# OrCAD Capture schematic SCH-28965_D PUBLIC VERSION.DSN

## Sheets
1 TITLE, TOC & REV: title: SEN-GEN6-SKT; rev: D; company: NXP Semiconductors; note: SCH-28965 PDF: SPF-28965; note: 6501 William Cannon Drive West; note: Austin, TX 78735-8598
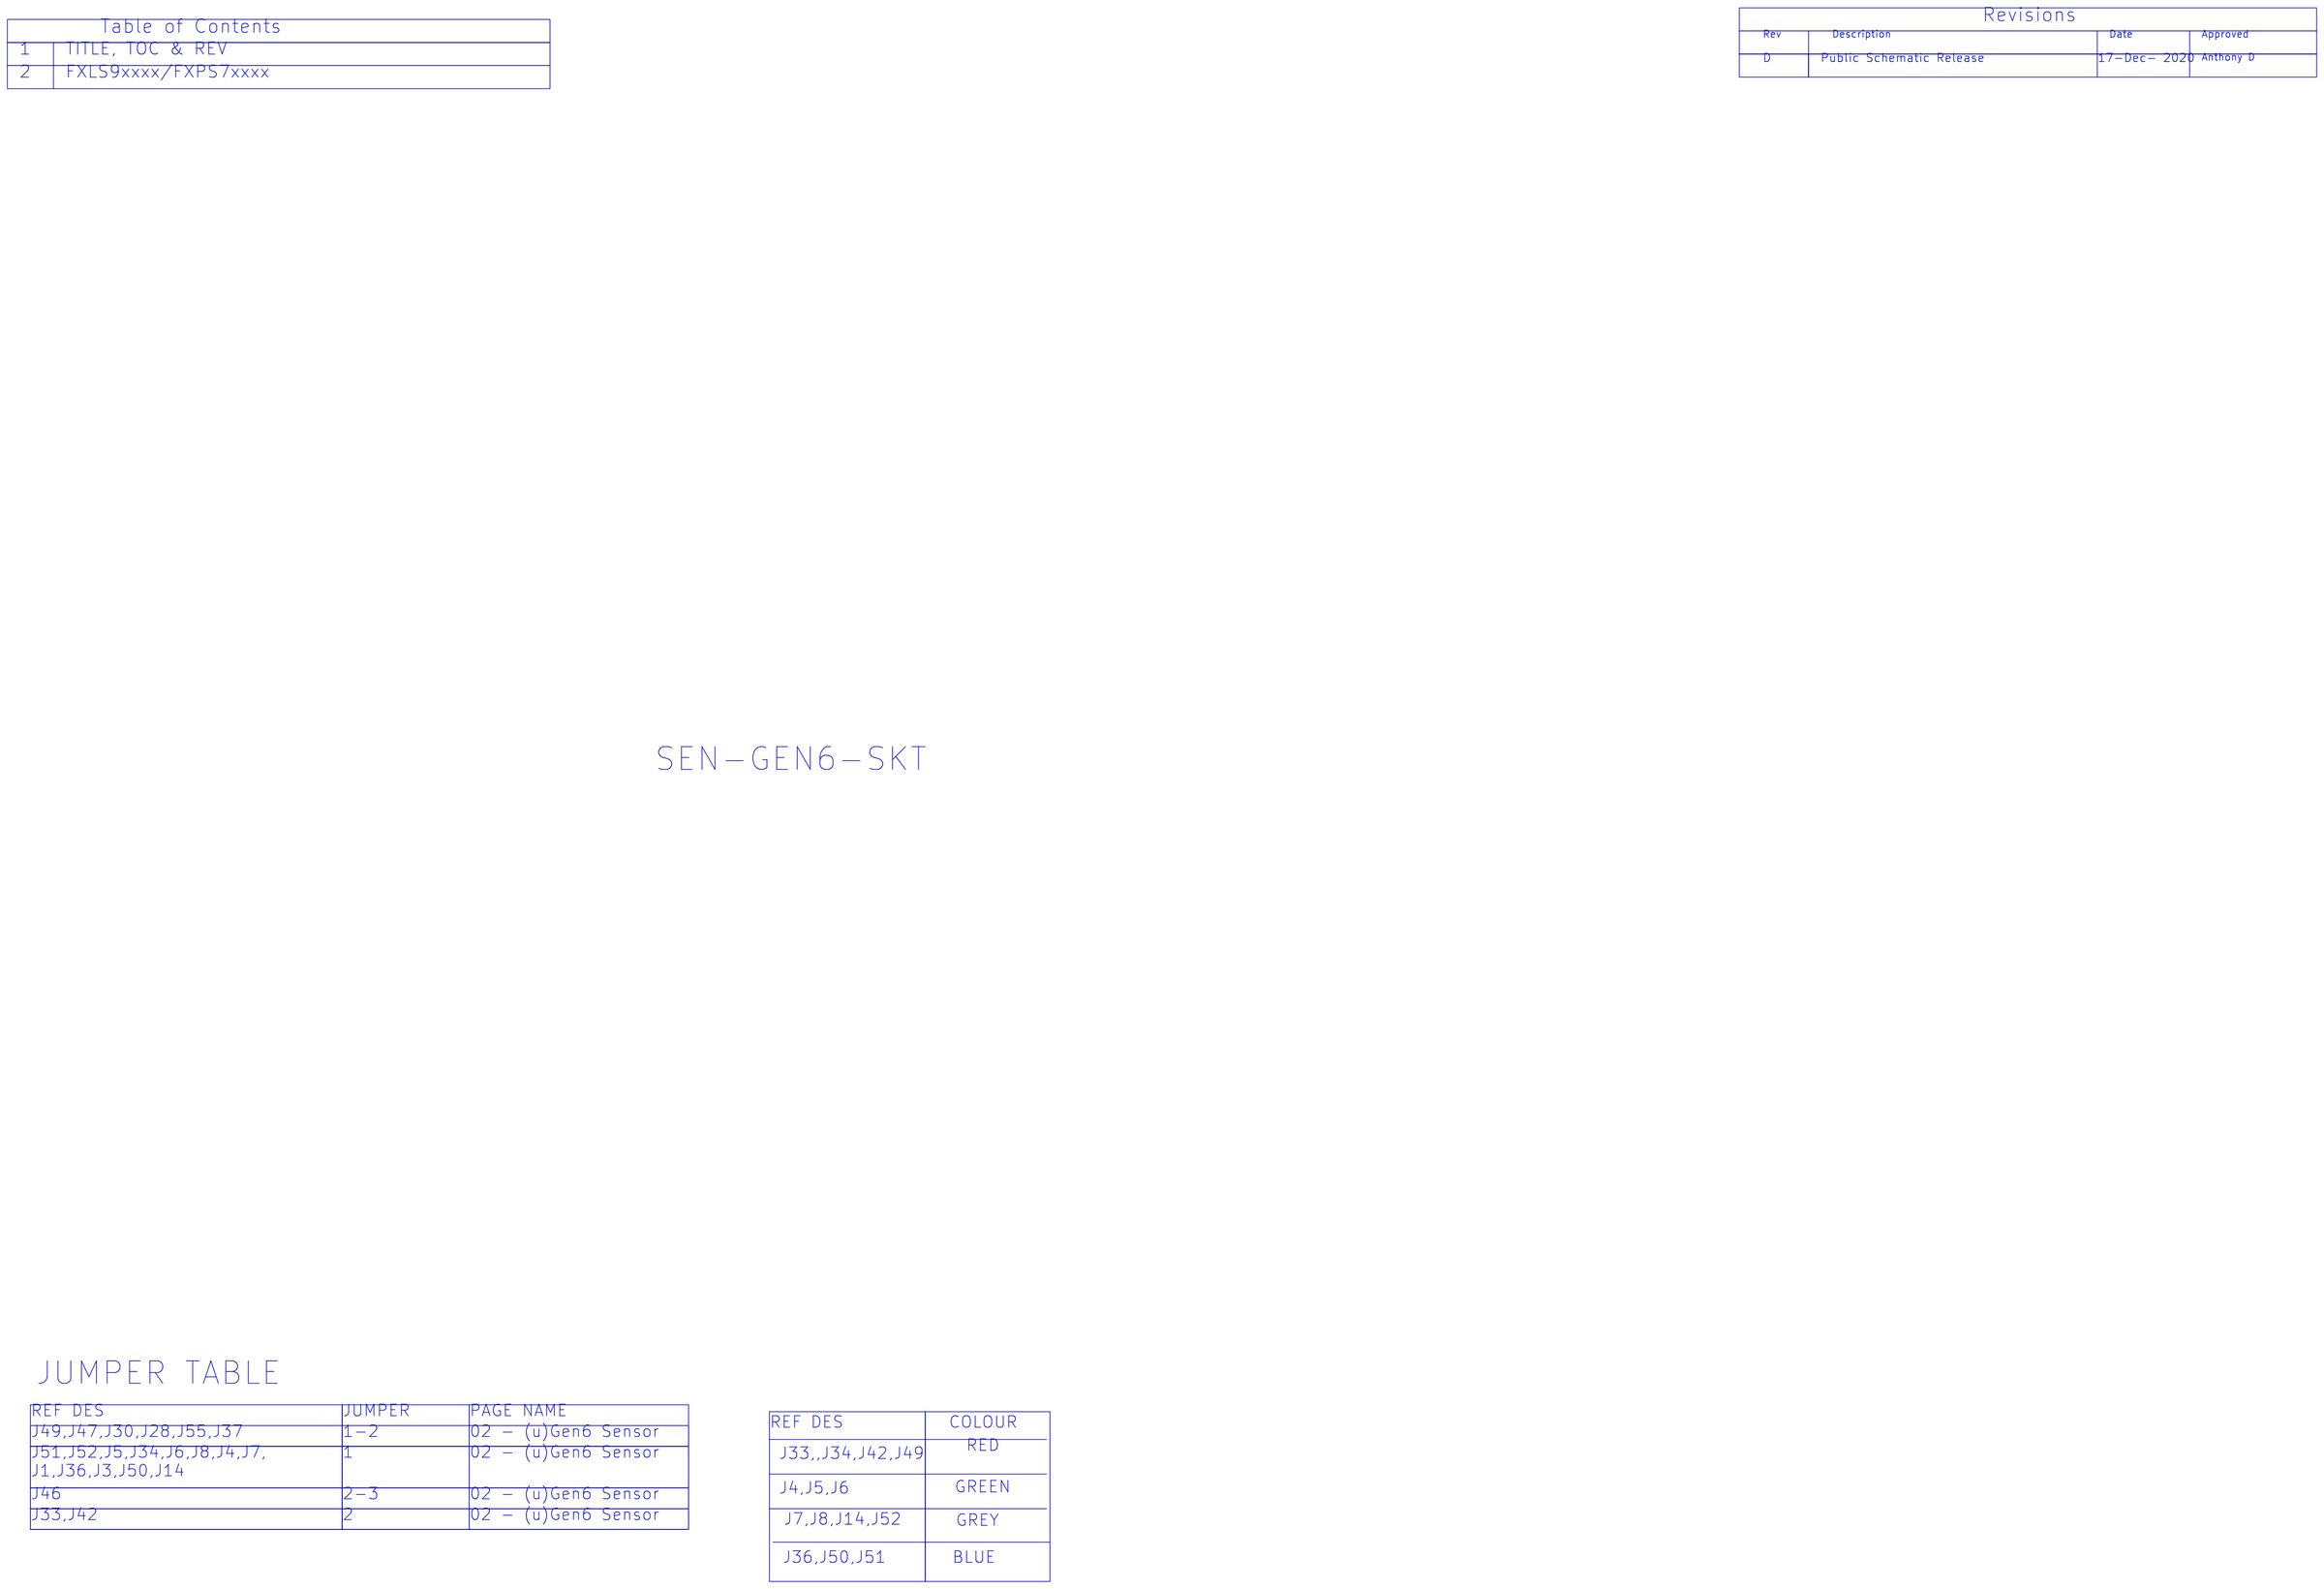
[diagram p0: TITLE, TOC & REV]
2 FXLS9xxxx/PXPS7xxxx: size C
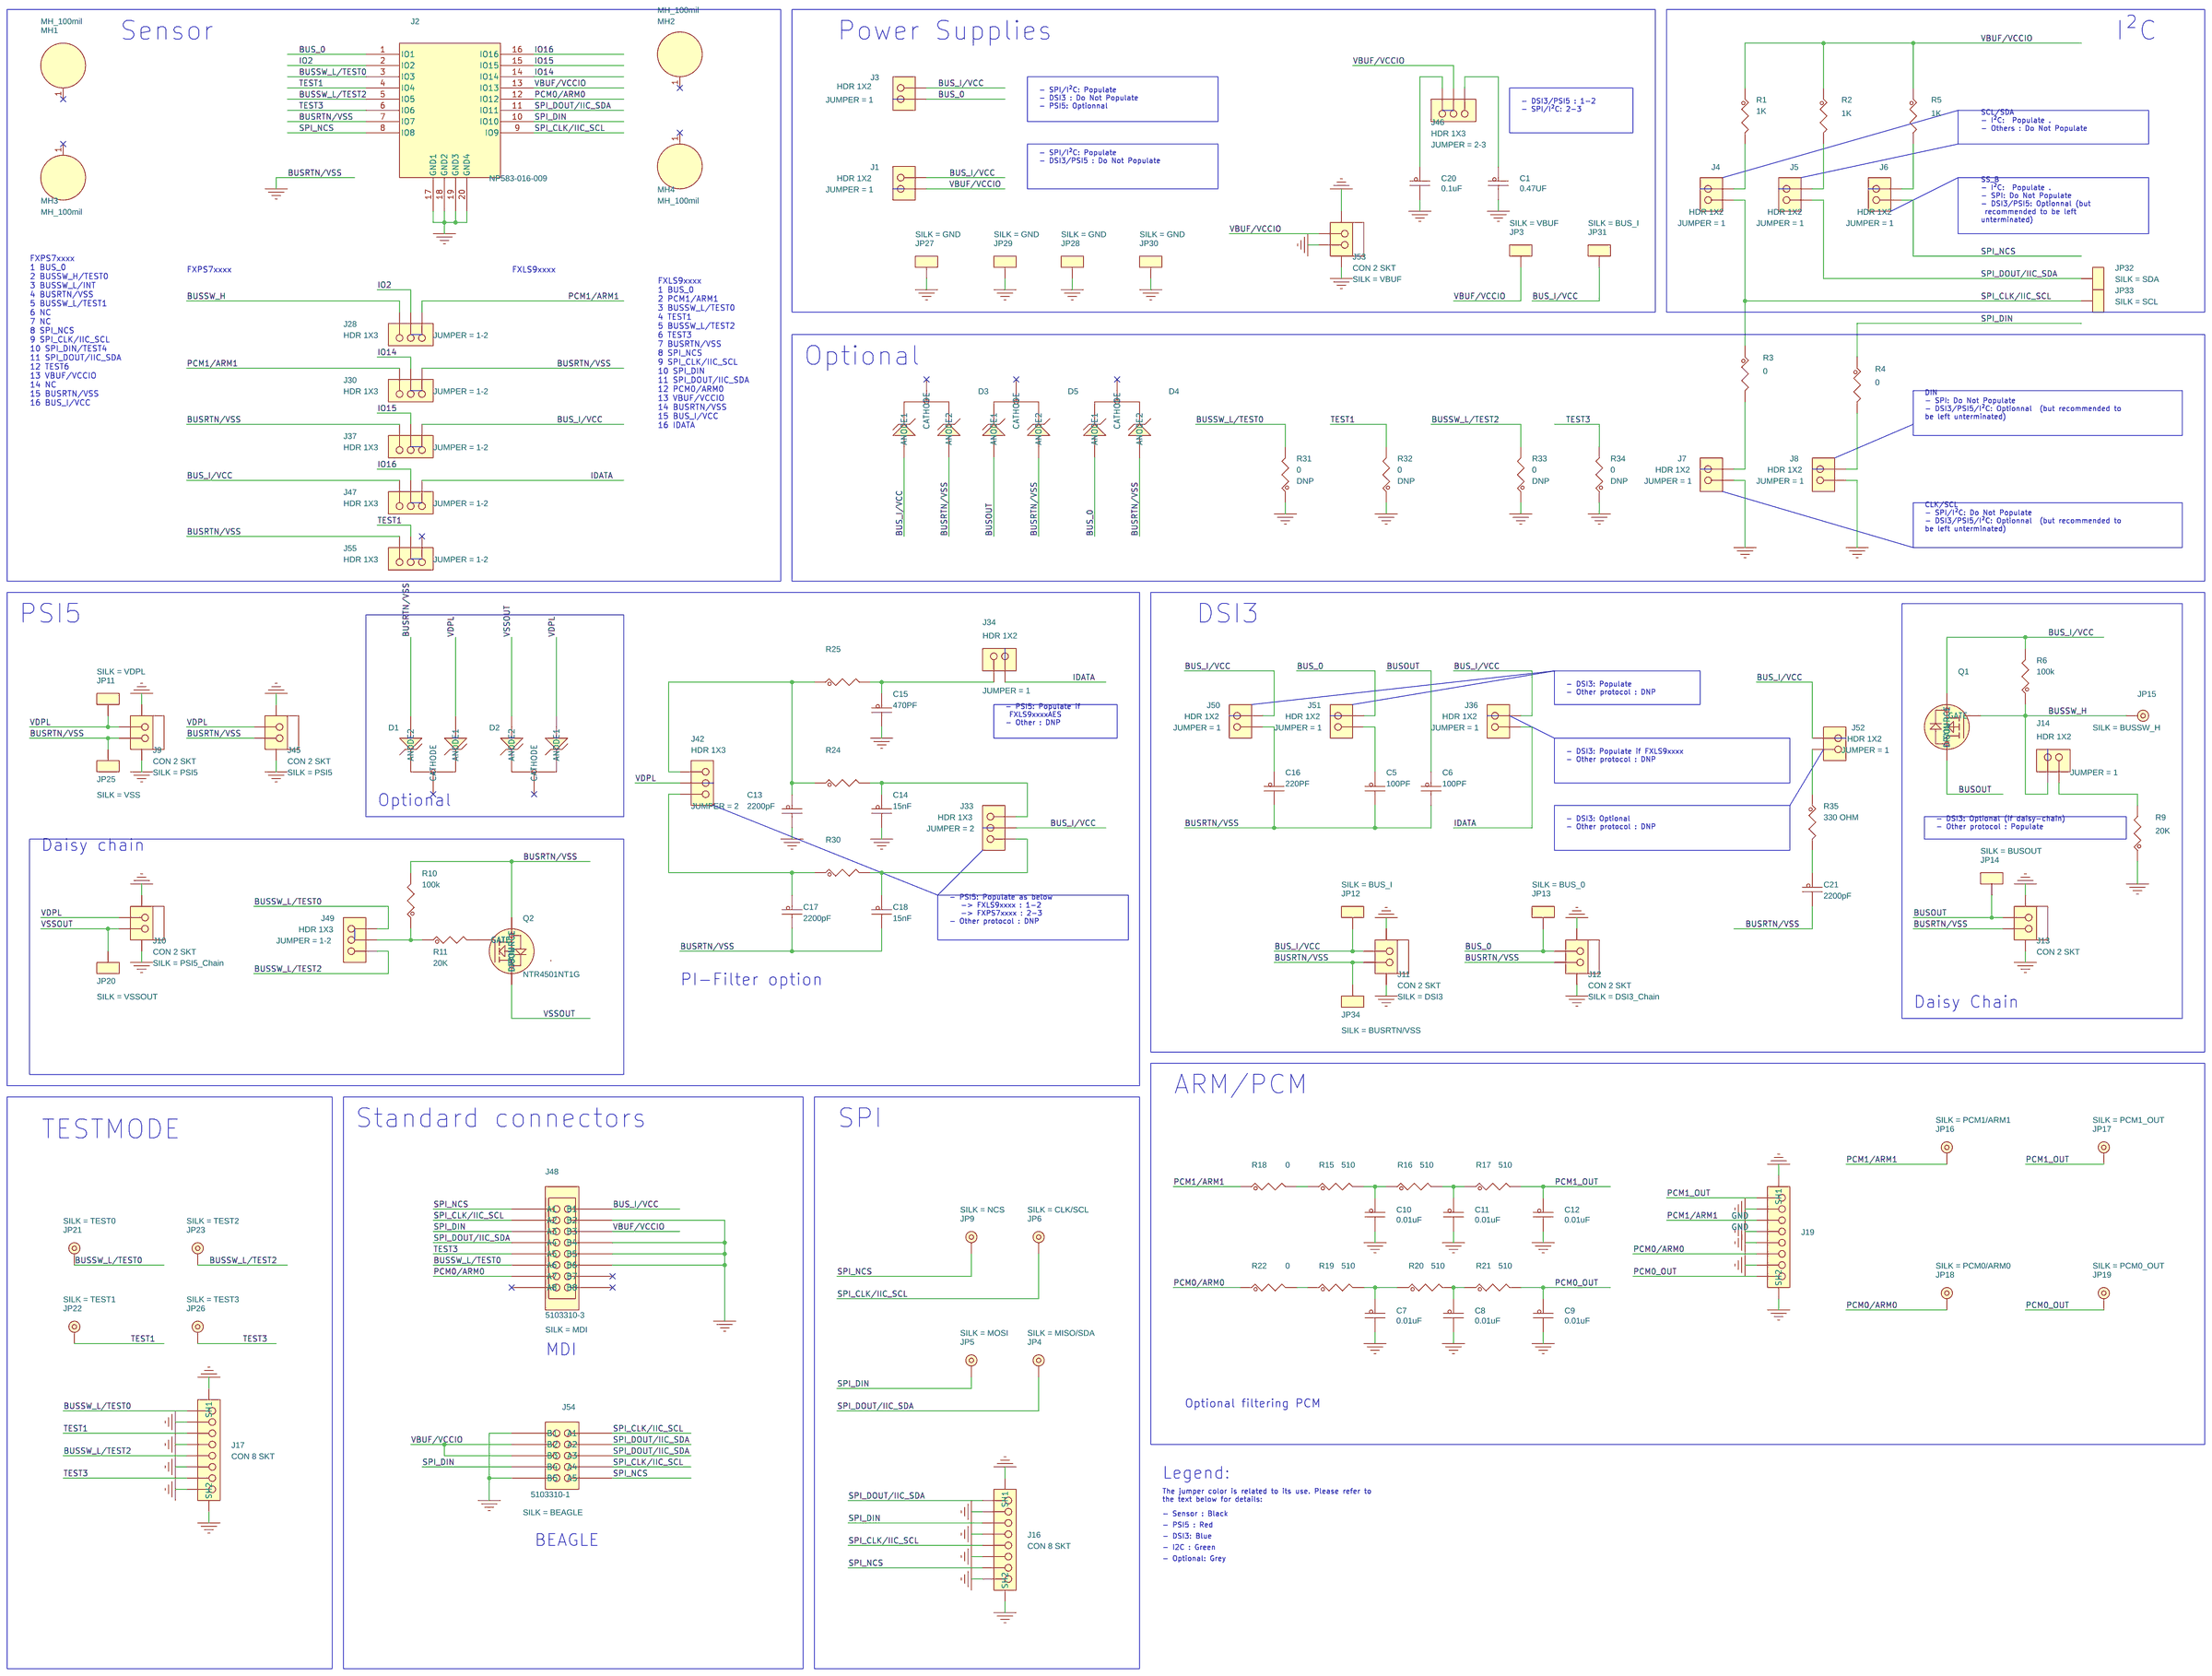
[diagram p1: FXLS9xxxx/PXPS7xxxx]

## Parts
C1  0.47UF  [CC0603_OV]
C5  100PF  [CC0603_OV]
C6  100PF  [CC0603_OV]
C7  0.01uF  [CC0402_25]
C8  0.01uF  [CC0402_25]
C9  0.01uF  [CC0402_25]
C10  0.01uF  [CC0402_25]
C11  0.01uF  [CC0402_25]
C12  0.01uF  [CC0402_25]
C13  2200pF  [CC0402_25]
C14  15nF  [CC0402_25]
C15  470PF  [CC0603_OV]
C16  220PF  [CC0603_OV]
C17  2200pF  [CC0402_25]
C18  15nF  [CC0402_25]
C20  0.1uF  [CC0603_OV]
C21  2200pF  [CC0402_25]
D1  MMBZ27VCLT1  [sot23_a]
D2  MMBZ27VCLT1  [sot23_a]
D3  MMBZ27VCLT1  [sot23_a]
D4  MMBZ27VCLT1  [sot23_a]
D5  MMBZ27VCLT1  [sot23_a]
J1  HDR 1X2  [HDR102]
J2  NP583-016-009  [skt_qfn16_0p8_25sq_th]
J3  HDR 1X2  [HDR102]
J4  HDR 1X2  [HDR102]
J5  HDR 1X2  [HDR102]
J6  HDR 1X2  [HDR102]
J7  HDR 1X2  [HDR102]
J8  HDR 1X2  [HDR102]
J9  CON 2 SKT  [con_2p_1mm_sm_4p2x3p3]
J10  CON 2 SKT  [con_2p_1mm_sm_4p2x3p3]
J11  CON 2 SKT  [con_2p_1mm_sm_4p2x3p3]
J12  CON 2 SKT  [con_2p_1mm_sm_4p2x3p3]
J13  CON 2 SKT  [con_2p_1mm_sm_4p2x3p3]
J14  HDR 1X2  [HDR102]
J16  CON 8 SKT  [con_8p_1mm_sm_10p2x3p3]
J17  CON 8 SKT  [con_8p_1mm_sm_10p2x3p3]
J19  CON 8 SKT  [con_8p_1mm_sm_10p2x3p3]
J28  HDR 1X3  [HDR103_A]
J30  HDR 1X3  [HDR103_A]
J33  HDR 1X3  [HDR103_A]
J34  HDR 1X2  [HDR102]
J36  HDR 1X2  [HDR102]
J37  HDR 1X3  [HDR103_A]
J42  HDR 1X3  [HDR103_A]
J45  CON 2 SKT  [con_2p_1mm_sm_4p2x3p3]
J46  HDR 1X3  [HDR103_A]
J47  HDR 1X3  [HDR103_A]
J48  5103310-3  [hdr_16m_100_th_ra]
J49  HDR 1X3  [HDR103_A]
J50  HDR 1X2  [HDR102]
J51  HDR 1X2  [HDR102]
J52  HDR 1X2  [HDR102]
J53  CON 2 SKT  [con_2p_1mm_sm_4p2x3p3]
J54  5103310-1  [hdr_10m_100_th_ra]
J55  HDR 1X3  [HDR103_A]
JP3  TEST_POINT  [tp_th_063]
JP4  5124  [tp_th_063]
JP5  5124  [tp_th_063]
JP6  5124  [tp_th_063]
JP9  5124  [tp_th_063]
JP11  TEST POINT  [tp_th_063]
JP12  TESTPOINT GREEN  [tp_th_063]
JP13  TESTPOINT GREEN  [tp_th_063]
JP14  TESTPOINT GREEN  [tp_th_063]
JP15  5007  [tp_th_063]
JP16  5007  [tp_th_063]
JP17  5124  [tp_th_063]
JP18  5007  [tp_th_063]
JP19  5124  [tp_th_063]
JP20  TEST POINT BLUE  [tp_th_063]
JP21  5007  [tp_th_063]
JP22  5007  [tp_th_063]
JP23  5007  [tp_th_063]
JP25  5006  [tp_th_063]
JP26  5007  [tp_th_063]
JP27  5006  [tp_th_063]
JP28  5006  [tp_th_063]
JP29  5006  [tp_th_063]
JP30  5006  [tp_th_063]
JP31  TEST_POINT  [tp_th_063]
JP32  TESTPOINT GREEN  [tp_th_063]
JP33  TESTPOINT GREEN  [tp_th_063]
JP34  TEST POINT BLUE  [tp_th_063]
MH1  MH_100mil  [c100-100n]
MH2  MH_100mil  [c100-100n]
MH3  MH_100mil  [c100-100n]
MH4  MH_100mil  [c100-100n]
Q1  NTR4502PT1G  [SOT23]
Q2  NTR4501NT1G  [SOT23-28X44]
R1  1K  [RC0402_25]
R2  1K  [RC0402_25]
R3  0  [RC0402_25]
R4  0  [RC0402_25]
R5  1K  [RC0402_25]
R6  100k  [RC0402_25]
R9  20K  [RC0402_25]
R10  100k  [RC0402_25]
R11  20K  [RC0402_25]
R15  510  [RC0402_25]
R16  510  [RC0402_25]
R17  510  [RC0402_25]
R18  0  [RC0402_25]
R19  510  [RC0402_25]
R20  510  [RC0402_25]
R21  510  [RC0402_25]
R22  0  [RC0402_25]
R24  82  [RC0603_OV]
R25  27.4  [RC0603_OV]
R30  27.4  [RC0603_OV]
R31  0  [RC0402_25]
R32  0  [RC0402_25]
R33  0  [RC0402_25]
R34  0  [RC0402_25]
R35  330 OHM  [RC0402_25]

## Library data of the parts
C1 = CAP_NP: CAP CER 0.47UF 16V 10% X7R 0603; AGILE_PN: 150-30233; CAD_APPROVED: Yes; FPLIST: CC0603_OV,CC0603,0603_CC; HEIGHT: 1mm; MFG_NAME01: KEMET; MFG_PN01: C0603C474K4RAC; Package Size: 0603; ROHS: Yes; Tolerance: 10%; VOLTAGE: 16V
C5 C6 = CAP_NP: CAP CER 100PF 50V 5% C0G 0603; AGILE_PN: 150-75286; CAD_APPROVED: Yes; FPLIST: CC0603_OV,CC0603,0603_CC; HEIGHT: 0.9mm; MFG_NAME01: AVX; MFG_PN01: 06035A101JAT2A; Package Size: 0603; Package Type: Tape & reel; ROHS: Yes; Tolerance: 5%; VOLTAGE: 50V
C7-C12 = CAP_NP: CAP CER 0.01uF 50V 10% X7R AEC-Q200 0402; AGILE_PN: 150-79051; CAD_APPROVED: Yes; FPLIST: CC0402_25,CC0402_HD,0402_CC; HEIGHT: 0.55MM; MFG_NAME01: MURATA; MFG_PN01: GCM155R71H103KA55D; Package Size: 0402; Package Type: 180mm Reel; ROHS: Yes; Tolerance: 10%; VOLTAGE: 50V
C13 C17 C21 = CAP_NP: CAP CER 2200pF 50V 10% X7R AEC-Q200 0402; AGILE_PN: 150-79020; CAD_APPROVED: Yes; FPLIST: CC0402_25,CC0402_HD,0402_CC; HEIGHT: 0.55MM; MFG_NAME01: MURATA; MFG_PN01: GCM155R71H222KA37D; Package Size: 0402; Package Type: ø180mm Reel PAPER; ROHS: Yes; Tolerance: 10%; VOLTAGE: 50V
C14 C18 = CAP_NP: CAP CER 15nF 50V 10% X7R AEC-Q200 0402; AGILE_PN: 150-79402; CAD_APPROVED: Yes; FPLIST: CC0402_25,CC0402_HD,0402_CC; HEIGHT: 0.55 MM; MFG_NAME01: MURATA; MFG_PN01: GCM155R71H153KA55; Package Size: 0402; ROHS: Yes; Tolerance: 15%; VOLTAGE: 50V
C15 = CAP_NP: CAP CER 470PF 50V 5% COG 0603; AGILE_PN: 150-75164; CAD_APPROVED: YES; FPLIST: CC0603_OV,CC0603,0603_CC; HEIGHT: 0.9 mm; MFG_NAME01: AVX; MFG_PN01: 06035A471JAT2A; Package Size: 0603; Package Type: Tape & reel; ROHS: Yes; Tolerance: 5%; VOLTAGE: 50VDC
C16 = CAP_NP: CAP CER 220PF 50V 5% C0G 0603; AGILE_PN: 150-75388; CAD_APPROVED: YES; FP_LIST: CC0603_OV,CC0603,0603_CC; HEIGHT: 0.9 mm; MFG_NAME01: AVX; MFG_PN01: 06035A221JAT2A; Package Size: 0603; ROHS: Yes; Tolerance: 5%; VOLTAGE: 50V
C20 = CAP_NP: CAP CER 0.1uF 50V 10% X7R AEC-Q200 0603; AGILE_PN: 150-79042; CAD_APPROVED: Yes; FPLIST: CC0603_OV,CC0603,0603_CC; HEIGHT: 0.9 MM; MFG_NAME01: AVX; MFG_PN01: 06035C104K4T2A; ROHS: Yes; Tolerance: 10%; VOLTAGE: 50V
D1-D5 = DZ_DUAL_CK_A1A2C: DIODE ZNR TVS -- 27V/40W SOT23; AGILE_PN: 480-78046; CAD_APPROVED: Yes; HEIGHT: 1.11MM; MFG_NAME01: ON SEMICONDUCTOR; MFG_PN01: MMBZ27VCLT1G; ROHS: Yes
J1 J3-J8 J14 J34 J36 J50-J52 = CONN_HDR_2X1: HDR 1X2 TH 100MIL SP 338H SN 100L; AGILE_PN: 210-80102; CAD_APPROVED: Yes; HEIGHT: 8.58MM; JUMPER: 1; MFG_NAME01: SAMTEC; MFG_PN01: TSW-102-07-T-S; Package Size: 5.08 x 2.54 mm; ROHS: Yes
J2 = QFNSOCKET16P_4PGND: SKT 16 QFN TH 0.8MM 555H -- 87L; AGILE_PN: 210-80686; CAD_APPROVED: Yes; HEIGHT: 14.1 MM; MFG_NAME01: YAMAICHI ELECTRONICS; Package Size: 25X25MM; Package Type: QFN; ROHS: Yes; SILK: BUSSW_H
J9 J45 = CONN_2X1_SH: CON 1X2 SIL SKT SHRD SMD 1MM SP 180H SN; AGILE_PN: 211-79243; CAD_APPROVED: Yes; HEIGHT: 4.55MM; MFG_NAME01: HARWIN INC; MFG_PN01: M40-3010246; ROHS: Yes; SILK: PSI5
J10 = CONN_2X1_SH: CON 1X2 SIL SKT SHRD SMD 1MM SP 180H SN; AGILE_PN: 211-79243; CAD_APPROVED: Yes; HEIGHT: 4.55MM; MFG_NAME01: HARWIN INC; MFG_PN01: M40-3010246; ROHS: Yes; SILK: PSI5_Chain
J11 = CONN_2X1_SH: CON 1X2 SIL SKT SHRD SMD 1MM SP 180H SN; AGILE_PN: 211-79243; CAD_APPROVED: Yes; HEIGHT: 4.55MM; MFG_NAME01: HARWIN INC; MFG_PN01: M40-3010246; ROHS: Yes; SILK: DSI3
J12 = CONN_2X1_SH: CON 1X2 SIL SKT SHRD SMD 1MM SP 180H SN; AGILE_PN: 211-79243; CAD_APPROVED: Yes; HEIGHT: 4.55MM; MFG_NAME01: HARWIN INC; MFG_PN01: M40-3010246; ROHS: Yes; SILK: DSI3_Chain
J13 = CONN_2X1_SH: CON 1X2 SIL SKT SHRD SMD 1MM SP 180H SN; AGILE_PN: 211-79243; CAD_APPROVED: Yes; HEIGHT: 4.55MM; MFG_NAME01: HARWIN INC; MFG_PN01: M40-3010246; ROHS: Yes; SILK: BUSOUT
J16 = CONN_8X1_SH: CON 1X8 SIL SKT SHRD SMT 1MM SP 180H SN; AGILE_PN: 211-79245; CAD_APPROVED: Yes; HEIGHT: 4.55MM; MFG_NAME01: HARWIN INC; MFG_PN01: M40-3010846; ROHS: Yes; SILK: SPI
J17 = CONN_8X1_SH: CON 1X8 SIL SKT SHRD SMT 1MM SP 180H SN; AGILE_PN: 211-79245; CAD_APPROVED: Yes; HEIGHT: 4.55MM; MFG_NAME01: HARWIN INC; MFG_PN01: M40-3010846; ROHS: Yes; SILK: TEST
J19 = CONN_8X1_SH: CON 1X8 SIL SKT SHRD SMT 1MM SP 180H SN; AGILE_PN: 211-79245; CAD_APPROVED: Yes; HEIGHT: 4.55MM; MFG_NAME01: HARWIN INC; MFG_PN01: M40-3010846; ROHS: Yes; SILK: PCM
J28 J30 J37 J47 J49 J55 = CONN_HDR_3X1: HDR 1X3 TH 2.54MM SP 344H AU 118L; AGILE_PN: 210-80732; CAD_APPROVED: Yes; HEIGHT: 8.74MM; JUMPER: 1-2; MFG_NAME01: WURTH ELEKTRONIK EISOS GMBH & CO. KG (ELECTRONIC & ELECTROMEHANICAL COMP); MFG_PN01: 61300311121; ROHS: Yes
J33 J42 = CONN_HDR_3X1: HDR 1X3 TH 2.54MM SP 344H AU 118L; AGILE_PN: 210-80732; CAD_APPROVED: Yes; HEIGHT: 8.74MM; JUMPER: 2; MFG_NAME01: WURTH ELEKTRONIK EISOS GMBH & CO. KG (ELECTRONIC & ELECTROMEHANICAL COMP); MFG_PN01: 61300311121; ROHS: Yes
J46 = CONN_HDR_3X1: HDR 1X3 TH 2.54MM SP 344H AU 118L; AGILE_PN: 210-80732; CAD_APPROVED: Yes; HEIGHT: 8.74MM; JUMPER: 2-3; MFG_NAME01: WURTH ELEKTRONIK EISOS GMBH & CO. KG (ELECTRONIC & ELECTROMEHANICAL COMP); MFG_PN01: 61300311121; ROHS: Yes
J48 = CONN_SHRHDR_8X2: CON 2X8 SHRD RA TH 100MIL CTR 365H AU 135L; 3D_Mechanical_Footprint_File: ftp://fcl.am.freescale.net/ALLEGRO/step/hdr_16m_100_th_ra.step; AGILE_PN: 210-79611; CAD_APPROVED: Yes; HEIGHT: 9.271 MM; MFG_NAME01: TYCO ELECTRONICS; ROHS: Yes; SILK: MDI
J53 = CONN_2X1_SH: CON 1X2 SIL SKT SHRD SMD 1MM SP 180H SN; AGILE_PN: 211-79243; CAD_APPROVED: Yes; HEIGHT: 4.55MM; MFG_NAME01: HARWIN INC; MFG_PN01: M40-3010246; ROHS: Yes; SILK: VBUF
J54 = CONN_HDR_5X2: HDR 2X5 TH RA 100MIL CTR 365H AU 135L; AGILE_PN: 210-81480; CAD_APPROVED: Yes; HEIGHT: 9.27MM; MFG_NAME01: TE Connectivity Ltd; ROHS: Yes; SILK: BEAGLE
JP3 = TEST_POINT: TEST POINT RED 70X220 MIL TH; AGILE_PN: 210-30156; CAD_APPROVED: Yes; FPLIST: tp_th_063,tp_th_063_nsp; HEIGHT: 5.59MM; MFG_NAME01: KEYSTONE ELECTRONICS; MFG_PN01: 5005; ROHS: Yes; SILK: VBUF
JP4 = T_POINT_TH: TEST POINT PURPLE 70X220 MIL TH; AGILE_PN: 210-80269; CAD_APPROVED: Yes; HEIGHT: 5.6 MM; MFG_NAME01: KEYSTONE ELECTRONICS; ROHS: Yes; SILK: MISO/SDA
JP5 = T_POINT_TH: TEST POINT PURPLE 70X220 MIL TH; AGILE_PN: 210-80269; CAD_APPROVED: Yes; HEIGHT: 5.6 MM; MFG_NAME01: KEYSTONE ELECTRONICS; ROHS: Yes; SILK: MOSI
JP6 = T_POINT_TH: TEST POINT PURPLE 70X220 MIL TH; AGILE_PN: 210-80269; CAD_APPROVED: Yes; HEIGHT: 5.6 MM; MFG_NAME01: KEYSTONE ELECTRONICS; ROHS: Yes; SILK: CLK/SCL
JP9 = T_POINT_TH: TEST POINT PURPLE 70X220 MIL TH; AGILE_PN: 210-80269; CAD_APPROVED: Yes; HEIGHT: 5.6 MM; MFG_NAME01: KEYSTONE ELECTRONICS; ROHS: Yes; SILK: NCS
JP11 = TEST_POINT: TEST POINT ORANGE 70X220 MIL TH; AGILE_PN: 210-80006; CAD_APPROVED: Yes; FPLIST: tp_th_063,tp_th_063_nsp; HEIGHT: 5.6MM; MFG_NAME01: KEYSTONE ELECTRONICS; MFG_PN01: 5008; ROHS: Yes; SILK: VDPL
JP12 = TEST_POINT: TEST POINT GREEN 70X220MIL TH; AGILE_PN: 210-80254; CAD_APPROVED: Yes; HEIGHT: 5.6 MM; MFG_NAME01: KEYSTONE ELECTRONICS; MFG_PN01: 5121; ROHS: Yes; SILK: BUS_I
JP13 = TEST_POINT: TEST POINT GREEN 70X220MIL TH; AGILE_PN: 210-80254; CAD_APPROVED: Yes; HEIGHT: 5.6 MM; MFG_NAME01: KEYSTONE ELECTRONICS; MFG_PN01: 5121; ROHS: Yes; SILK: BUS_0
JP14 = TEST_POINT: TEST POINT GREEN 70X220MIL TH; AGILE_PN: 210-80254; CAD_APPROVED: Yes; HEIGHT: 5.6 MM; MFG_NAME01: KEYSTONE ELECTRONICS; MFG_PN01: 5121; ROHS: Yes; SILK: BUSOUT
JP15 = T_POINT_TH: TEST POINT WHITE 70X220 MIL TH; AGILE_PN: 210-80268; CAD_APPROVED: Yes; HEIGHT: 5.6 MM; MFG_NAME01: KEYSTONE ELECTRONICS; ROHS: Yes; SILK: BUSSW_H
JP16 = T_POINT_TH: TEST POINT WHITE 70X220 MIL TH; AGILE_PN: 210-80268; CAD_APPROVED: Yes; HEIGHT: 5.6 MM; MFG_NAME01: KEYSTONE ELECTRONICS; ROHS: Yes; SILK: PCM1/ARM1
JP17 = T_POINT_TH: TEST POINT PURPLE 70X220 MIL TH; AGILE_PN: 210-80269; CAD_APPROVED: Yes; HEIGHT: 5.6 MM; MFG_NAME01: KEYSTONE ELECTRONICS; ROHS: Yes; SILK: PCM1_OUT
JP18 = T_POINT_TH: TEST POINT WHITE 70X220 MIL TH; AGILE_PN: 210-80268; CAD_APPROVED: Yes; HEIGHT: 5.6 MM; MFG_NAME01: KEYSTONE ELECTRONICS; ROHS: Yes; SILK: PCM0/ARM0
JP19 = T_POINT_TH: TEST POINT PURPLE 70X220 MIL TH; AGILE_PN: 210-80269; CAD_APPROVED: Yes; HEIGHT: 5.6 MM; MFG_NAME01: KEYSTONE ELECTRONICS; ROHS: Yes; SILK: PCM0_OUT
JP20 = TEST_POINT: TEST POINT BLUE 70X220MIL TH; AGILE_PN: 210-80250; CAD_APPROVED: Yes; HEIGHT: 5.6MM; MFG_NAME01: KEYSTONE ELECTRONICS; MFG_PN01: 5122; Package Size: 125 MIL DIA; ROHS: Yes; SILK: VSSOUT
JP21 = T_POINT_TH: TEST POINT WHITE 70X220 MIL TH; AGILE_PN: 210-80268; CAD_APPROVED: Yes; HEIGHT: 5.6 MM; MFG_NAME01: KEYSTONE ELECTRONICS; ROHS: Yes; SILK: TEST0
JP22 = T_POINT_TH: TEST POINT WHITE 70X220 MIL TH; AGILE_PN: 210-80268; CAD_APPROVED: Yes; HEIGHT: 5.6 MM; MFG_NAME01: KEYSTONE ELECTRONICS; ROHS: Yes; SILK: TEST1
JP23 = T_POINT_TH: TEST POINT WHITE 70X220 MIL TH; AGILE_PN: 210-80268; CAD_APPROVED: Yes; HEIGHT: 5.6 MM; MFG_NAME01: KEYSTONE ELECTRONICS; ROHS: Yes; SILK: TEST2
JP25 = TEST_POINT: TEST POINT BLK 70X220 MIL TH; AGILE_PN: 210-30155; CAD_APPROVED: Yes; FPLIST: tp_th_063,tp_th_063_nsp; HEIGHT: 5.6MM; MFG_NAME01: KEYSTONE ELECTRONICS; ROHS: Yes; SILK: VSS
JP26 = T_POINT_TH: TEST POINT WHITE 70X220 MIL TH; AGILE_PN: 210-80268; CAD_APPROVED: Yes; HEIGHT: 5.6 MM; MFG_NAME01: KEYSTONE ELECTRONICS; ROHS: Yes; SILK: TEST3
JP27-JP30 = TEST_POINT: TEST POINT BLK 70X220 MIL TH; AGILE_PN: 210-30155; CAD_APPROVED: Yes; FPLIST: tp_th_063,tp_th_063_nsp; HEIGHT: 5.6MM; MFG_NAME01: KEYSTONE ELECTRONICS; ROHS: Yes; SILK: GND
JP31 = TEST_POINT: TEST POINT RED 70X220 MIL TH; AGILE_PN: 210-30156; CAD_APPROVED: Yes; FPLIST: tp_th_063,tp_th_063_nsp; HEIGHT: 5.59MM; MFG_NAME01: KEYSTONE ELECTRONICS; MFG_PN01: 5005; ROHS: Yes; SILK: BUS_I
JP32 = TEST_POINT: TEST POINT GREEN 70X220MIL TH; AGILE_PN: 210-80254; CAD_APPROVED: Yes; HEIGHT: 5.6 MM; MFG_NAME01: KEYSTONE ELECTRONICS; MFG_PN01: 5121; ROHS: Yes; SILK: SDA
JP33 = TEST_POINT: TEST POINT GREEN 70X220MIL TH; AGILE_PN: 210-80254; CAD_APPROVED: Yes; HEIGHT: 5.6 MM; MFG_NAME01: KEYSTONE ELECTRONICS; MFG_PN01: 5121; ROHS: Yes; SILK: SCL
JP34 = TEST_POINT: TEST POINT BLUE 70X220MIL TH; AGILE_PN: 210-80250; CAD_APPROVED: Yes; HEIGHT: 5.6MM; MFG_NAME01: KEYSTONE ELECTRONICS; MFG_PN01: 5122; Package Size: 125 MIL DIA; ROHS: Yes; SILK: BUSRTN/VSS
MH1-MH4 = Mounting_Hole_1P: MOUNTING HOLE NON-PLATED 100MIL TH  NO PART TO ORDER; AGILE_PN: 280-76459; CAD_APPROVED: Yes; HEIGHT: 0.1MM; MFG_NAME01: NA; MFG_PN01: Tooling Hole - 100 Mil drill NPTH; ROHS: Not Applicable
Q1 = MOSFET_P: TRAN PMOS PWR 30V 1.95A SOT23; AGILE_PN: 480-78173; CAD_APPROVED: Yes; HEIGHT: 1.11MM; MFG_NAME01: ON Semiconductor; ROHS: Yes
Q2 = MOSFET_N: TRAN N CHNL MOSFET SGL PWR 20V 3.2A SOT23; AGILE_PN: 480-75480; CAD_APPROVED: Yes; HEIGHT: 1.11mm; MFG_NAME01: ON SEMICONDUCTOR; ROHS: Yes
R1 R2 R5 = RES: RES MF 1K 1/16W 0.5% 0402; AGILE_PN: 470-80057; CAD_APPROVED: Yes; FPLIST: RC0402_25,RC0402_HD,0402_CC; HEIGHT: 0.4MM; MFG_NAME01: Panasonic; MFG_PN01: ERA2AED102X; ROHS: Yes; Tolerance: 0.5%
R3 R4 R18 R22 = RES: RES TF ZERO  OHM 1/16W AEC-Q200 RC0402; AGILE_PN: 470-75366; CAD_APPROVED: Yes; FPLIST: RC0402_25,RC0402_HD,0402_CC; HEIGHT: 0.35mm; MFG_NAME01: VISHAY INTERTECHNOLOGY; MFG_PN01: CRCW04020000ZS; ROHS: Yes; Tolerance: 5%
R6 R10 = RES: RES MF 100k Ohm 1/16W 1% AEC-Q200 0402; AGILE_PN: 470-80502; CAD_APPROVED: Yes; FPLIST: RC0402_25,RC0402_HD,0402_CC; HEIGHT: 0.4 MM; MFG_NAME01: KOA SPEER; MFG_PN01: RK73H1ETTP1003F; ROHS: Yes; Tolerance: 1%
R9 R11 = RES: RES MF 20K 1/16W 1% AEC-Q200 0402; AGILE_PN: 470-80743; CAD_APPROVED: Yes; FPLIST: RC0402_25,RC0402_HD,0402_CC; HEIGHT: 0.4MM; MFG_NAME01: VISHAY INTERTECHNOLOGY; MFG_PN01: CRCW040220K0FKED; ROHS: Yes
R15-R17 R19-R21 = RES: RES MF 510 OHM 1/16W 1% AEC-Q200 0402; AGILE_PN: 470-80725; CAD_APPROVED: Yes; FPLIST: RC0402_25,RC0402_HD,0402_CC; HEIGHT: 0.4 MM; MFG_NAME01: VISHAY INTERTECHNOLOGY; MFG_PN01: CRCW0402510RFKED; ROHS: Yes; Tolerance: 1%
R24 = RES: RES MF 82.0 OHM 1/10W 1% 0603; AGILE_PN: 470-76042; CAD_APPROVED: Yes; FPLIST: RC0603_OV,RC0603,0603_CC; HEIGHT: 0.55 MM; MFG_NAME01: BOURNS; MFG_PN01: CR0603-FX-82R0ELF; ROHS: Yes; Tolerance: 1%
R25 R30 = RES: RES MF 27.4 OHM 1/8W 1% AEC-Q200 0603; AGILE_PN: 470-77865; CAD_APPROVED: Yes; FPLIST: RC0603_OV,RC0603,0603_CC; HEIGHT: 0.55MM; MFG_NAME01: KOA SPEER; MFG_PN01: RK73H1JTTD27R4F; ROHS: Yes; Temp Range: -55C to +155C; Tolerance: 1%
R31-R34 = RES: RES TF ZERO  OHM 1/16W AEC-Q200 RC0402; AGILE_PN: 470-75366; ASSY_OPT: DNP; CAD_APPROVED: Yes; FPLIST: RC0402_25,RC0402_HD,0402_CC; HEIGHT: 0.35mm; MFG_NAME01: VISHAY INTERTECHNOLOGY; MFG_PN01: CRCW04020000ZS; ROHS: Yes; Tolerance: 5%
R35 = RES: RES MF 330 OHM 1/16W 1% 0402; AGILE_PN: 470-80566; CAD_APPROVED: Yes; FPLIST: RC0402_25,RC0402_HD,0402_CC; HEIGHT: 0.4MM; MFG_NAME01: WALSIN TECHNOLOGY CORP.; MFG_PN01: WR04X3300FTL; ROHS: Yes; Tolerance: 1%

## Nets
BUS_I/VCC: D3.1(ANODE1) J1.2 J3.1 J11.2 J33.2 J36.1 J37.1 J47.3 J48.2(B1) J50.1 J52.1 JP12.1 JP31.1 Q1.2(SOURCE) R6.2
GND: C1.2 C5.2 C6.2 C7.2 C8.2 C9.2 C10.2 C11.2 C12.2 C13.2 C14.2 C15.2 C16.2 C17.2 C18.2 C20.2 C21.2 D1.2(ANODE2) D3.2(ANODE2) D4.2(ANODE2) D5.2(ANODE2) J2.7(IO7) J2.17(GND1) J2.18(GND2) J2.19(GND3) J2.20(GND4) J7.2 J8.2 J9.1 J9.S1 J9.S2 J10.S1 J10.S2 J11.1 J11.S1 J11.S2 J12.1 J12.S1 J12.S2 J13.1 J13.S1 J13.S2 J16.2 J16.4 J16.6 J16.8 J16.S1(SH1) J16.S2(SH2) J17.2 J17.4 J17.6 J17.8 J17.S1(SH1) J17.S2(SH2) J19.2 J19.4 J19.5 J19.7 J19.S1(SH1) J19.S2(SH2) J30.1 J37.3 J45.1 J45.S1 J45.S2 J48.4(B2) J48.8(B4) J48.10(B5) J48.12(B6) J53.1 J53.S1 J53.S2 J54.2(B1) J54.10(B5) J55.3 JP25.1 JP27.1 JP28.1 JP29.1 JP30.1 JP34.1 Q2.2(SOURCE) R9.1 R10.2 R31.1 R32.1 R33.1 R34.1
VBUF/VCCIO: J1.1 J2.13(IO13) J46.2 J48.6(B3) J53.2 J54.4(B2) J54.6(B3) JP3.1 R1.1 R2.1 R5.1
VSSOUT: D2.2(ANODE2) J10.1 JP20.1 Q2.3(DRAIN)
BUS_0: D4.1(ANODE1) J2.1(IO1) J3.2 J12.2 J51.1 JP13.1
BUSOUT: C6.1 D5.1(ANODE1) J13.2 JP14.1 Q1.3(DRAIN)
BUSSW_H: J14.1 J28.3 JP15.1(TP) Q1.1(GATE) R6.1
BUSSW_L/TEST0: J2.3(IO3) J17.1 J48.11(A6) J49.1 JP21.1(TP) R31.2
BUSSW_L/TEST2: J2.5(IO5) J17.5 J49.3 JP23.1(TP) R33.2
IDATA: J34.1 J36.2 J47.1
IO2: J2.2(IO2) J28.2
IO14: J2.14(IO14) J30.2
IO15: J2.15(IO15) J37.2
IO16: J2.16(IO16) J47.2
PCM0/ARM0: J2.12(IO12) J19.6 J48.13(A7) JP18.1(TP) R22.1
PCM0_OUT: C9.1 J19.8 JP19.1(TP) R21.2
PCM1/ARM1: J19.3 J28.1 J30.3 JP16.1(TP) R18.1
PCM1_OUT: C12.1 J19.1 JP17.1(TP) R17.2
SPI_CLK/IIC_SCL: J2.9(IO9) J4.2 J16.5 J48.3(A2) J54.1(A1) J54.7(A4) JP6.1(TP) JP33.1 R3.1
SPI_DIN: J2.10(IO10) J16.3 J48.5(A3) J54.8(B4) JP5.1(TP) R4.1
SPI_DOUT/IIC_SDA: J2.11(IO11) J5.2 J16.1 J48.7(A4) J54.3(A2) J54.5(A3) JP4.1(TP) JP32.1
SPI_NCS: J2.8(IO8) J6.2 J16.7 J48.1(A1) J54.9(A5) JP9.1(TP)
TEST1: J2.4(IO4) J17.3 J55.2 JP22.1(TP) R32.2
TEST3: J2.6(IO6) J17.7 J48.9(A5) JP26.1(TP) R34.2
VDPL: D1.1(ANODE1) D2.1(ANODE1) J9.2 J10.2 J42.2 J45.2 JP11.1
N16262320: J49.2 R10.1 R11.1
N16263932: C16.1 J50.2
N16629501: C11.1 R16.2 R17.1
N16629509: C10.1 R15.2 R16.1
N16629513: R15.1 R18.2
N16629717: C7.1 R19.2 R20.1
N16629725: C8.1 R20.2 R21.1
N16629777: R19.1 R22.2
N16685534: C14.1 J33.1 R24.2
N16685548: C13.1 J42.1 R24.1 R25.1
N16686513: C15.1 J34.2 R25.2
N16749782: C17.1 J42.3 R30.1
N16749849: C18.1 J33.3 R30.2
N16830665: J8.1 R4.2
N16830677: J7.1 R3.2
N16834962: C1.1 J46.1
N16835010: C20.1 J46.3
N16854681: C21.1 R35.2
N16859991: J6.1 R5.2
N16860108: J4.1 R1.2
N16860113: J5.1 R2.2
N16862292: C5.1 J51.2
N16864132: J52.2 R35.1
N16864682: J14.2 R9.2
N16928943: Q2.1(GATE) R11.2

Not connected (* = marked no-connect by the designer): D1 3(CATHODE)*; D2 3(CATHODE)*; D3 3(CATHODE)*; D4 3(CATHODE)*; D5 3(CATHODE)*; J48 14(B7)* 15(A8)* 16(B8)*; J55 1*; MH1 1*; MH2 1*; MH3 1*; MH4 1*

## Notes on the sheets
sheet 1
- Revisions
- Table of Contents
- Rev
- Description
- Date
- Approved
- 1
- TITLE, TOC & REV
- D
- Public Schematic Release
- 17-Dec- 2020
- Anthony D
- 2
- FXLS9xxxx/FXPS7xxxx
- SEN-GEN6-SKT
- JUMPER TABLE
- REF DES
- JUMPER
- PAGE NAME
- REF DES
- COLOUR
- J49,J47,J30,J28,J55,J37
- 1-2
- 02 - (u)Gen6 Sensor
- RED
- J51,J52,J5,J34,J6,J8,J4,J7,
  J1,J36,J3,J50,J14
- 1
- 02 - (u)Gen6 Sensor
- J33,,J34,J42,J49
- J4,J5,J6
- GREEN
- J46
- 2-3
- 02 - (u)Gen6 Sensor
- J33,J42
- 2
- 02 - (u)Gen6 Sensor
- J7,J8,J14,J52
- GREY
- J36,J50,J51
- BLUE
sheet 2
- Sensor
- Power Supplies
- I²C
- - SPI/I²C: Populate
  - DSI3 : Do Not Populate
  - PSI5: Optionnal
- - DSI3/PSI5 : 1-2
  - SPI/I²C: 2-3
- SCL/SDA
  - I²C:  Populate .
  - Others : Do Not Populate
- - SPI/I²C: Populate
  - DSI3/PSI5 : Do Not Populate
- SS_B
  - I²C:  Populate .
  - SPI: Do Not Populate
  - DSI3/PSI5: Optionnal (but
   recommended to be left
  unterminated)
- FXPS7xxxx
  1 BUS_0
  2 BUSSW_H/TEST0
  3 BUSSW_L/INT
  4 BUSRTN/VSS
  5 BUSSW_L/TEST1
  6 NC
  7 NC
  8 SPI_NCS
  9 SPI_CLK/IIC_SCL
  10 SPI_DIN/TEST4
  11 SPI_DOUT/IIC_SDA
  12 TEST6
  13 VBUF/VCCIO
  14 NC
  15 BUSRTN/VSS
  16 BUS_I/VCC
- FXPS7xxxx
- FXLS9xxxx
- FXLS9xxxx
  1 BUS_0
  2 PCM1/ARM1
  3 BUSSW_L/TEST0
  4 TEST1
  5 BUSSW_L/TEST2
  6 TEST3
  7 BUSRTN/VSS
  8 SPI_NCS
  9 SPI_CLK/IIC_SCL
  10 SPI_DIN
  11 SPI_DOUT/IIC_SDA
  12 PCM0/ARM0
  13 VBUF/VCCIO
  14 BUSRTN/VSS
  15 BUS_I/VCC
  16 IDATA
- Optional
- DIN
  - SPI: Do Not Populate
  - DSI3/PSI5/I²C: Optionnal  (but recommended to
  be left unterminated)
- CLK/SCL
  - SPI/I²C: Do Not Populate
  - DSI3/PSI5/I²C: Optionnal  (but recommended to
  be left unterminated)
- PSI5
- DSI3
- - DSI3: Populate
  - Other protocol : DNP
- - PSI5: Populate if
   FXLS9xxxxAES
  - Other : DNP
- - DSI3: Populate if FXLS9xxxx
  - Other protocol : DNP
- Optional
- - DSI3: Optional
  - Other protocol : DNP
- - DSI3: Optional (if daisy-chain)
  - Other protocol : Populate
- Daisy chain
- - PSI5: Populate as below
     -> FXLS9xxxx : 1-2
     -> FXPS7xxxx : 2-3
  - Other protocol : DNP
- PI-Filter option
- Daisy Chain
- ARM/PCM
- Standard connectors
- SPI
- TESTMODE
- MDI
- Optional filtering PCM
- Legend:
- The jumper color is related to its use. Please refer to
  the text below for details:
- - Sensor : Black
- - PSI5 : Red
- BEAGLE
- - DSI3: Blue
- - I2C : Green
- - Optional: Grey
